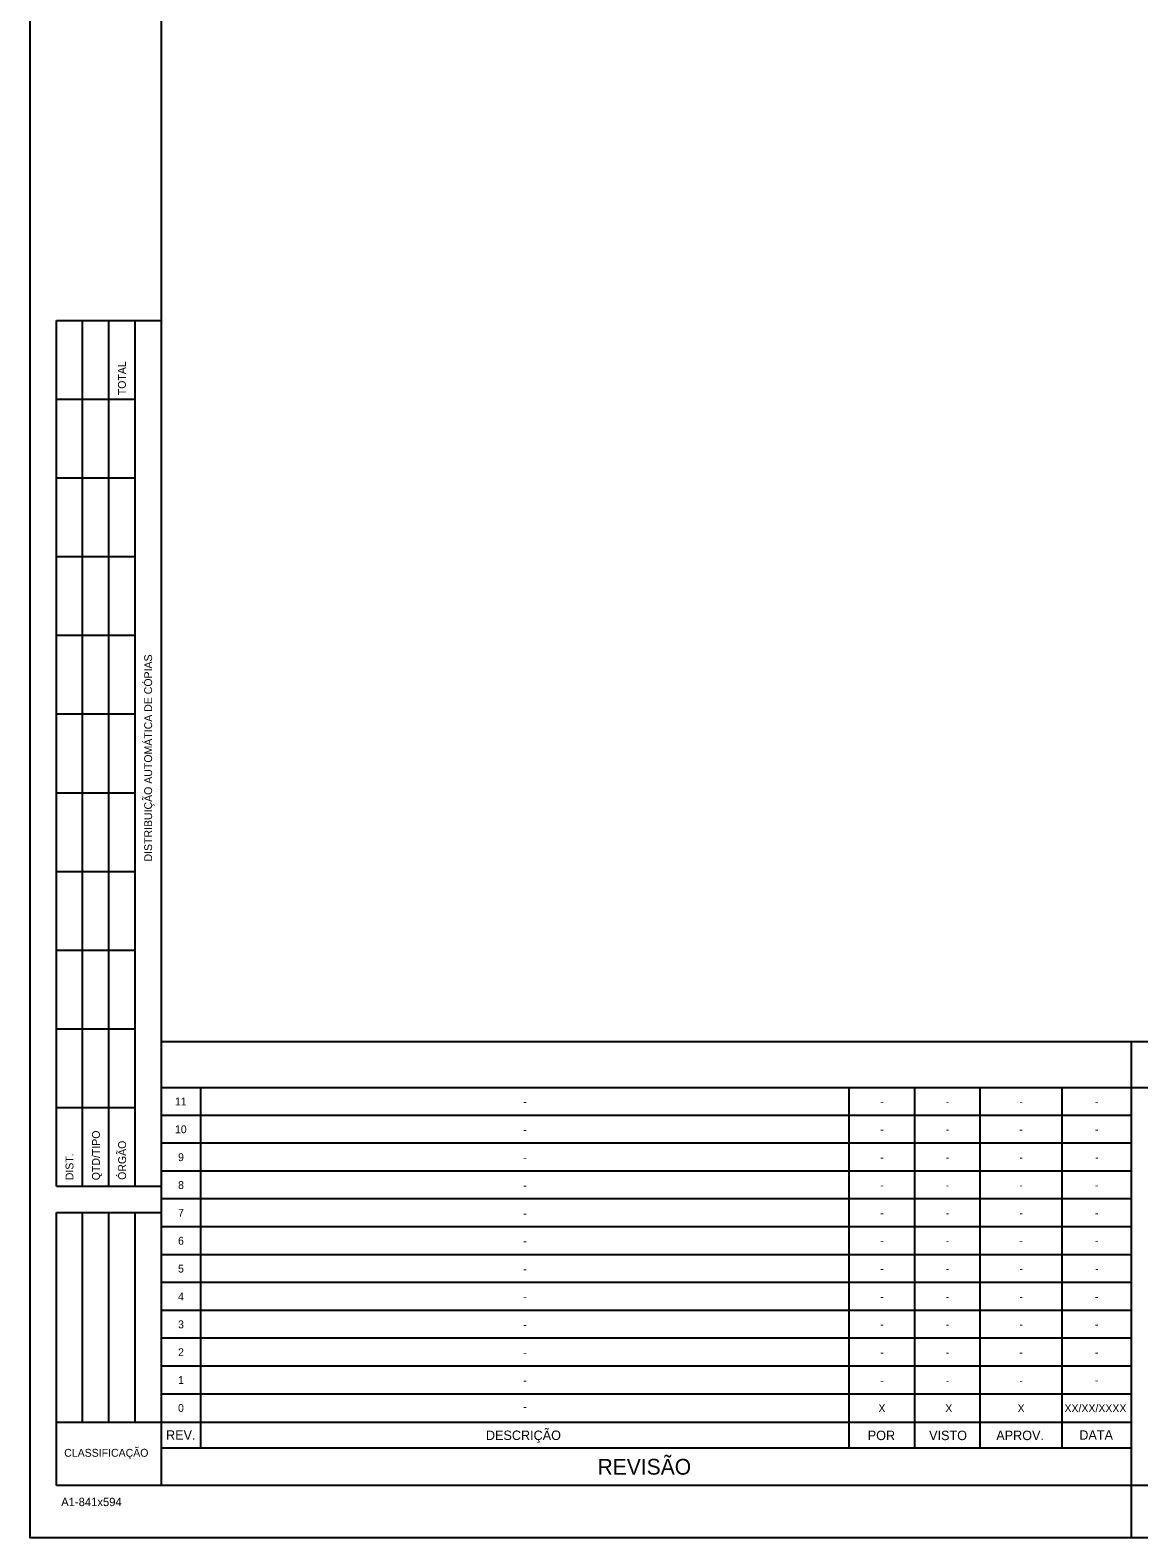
# Model space of a CAD drawing. Extents: x -1349 to -508, y 286 to 880.
# Drawn here: x -1349 to -1137.7, y 285.8 to 573.1 of the extents above; entities that cross this region are included whole.
import ezdxf

# ---------------------------------------------------------------- set-up
doc = ezdxf.new("R2010")
doc.units = 0
doc.layers.add('FORMATO', color=7, linetype='Continuous')
doc.layers.add('TEXTO', color=7, linetype='Continuous')

msp = doc.modelspace()

# ---------------------------------------------------------------- linework, layer by layer
at = {"layer": 'FORMATO'}
msp.add_line((-518.04, 295.82), (-1344.05, 295.82), dxfattribs=at)
msp.add_lwpolyline([(-1349.05, 879.82), (-508.05, 879.82), (-508.05, 285.82), (-1349.05, 285.82)], close=True, dxfattribs=at)
for points in [[(-518.04, 295.82), (-518.04, 869.82), (-1324.05, 869.82), (-1324.05, 295.82)], [(-1344.05, 352.82), (-1344.05, 517.82)], [(-1344.05, 517.82), (-1324.05, 517.82)], [(-1339.05, 352.82), (-1339.05, 517.82)], [(-1334.05, 352.82), (-1334.05, 517.82)], [(-1329.05, 352.82), (-1329.05, 517.82)], [(-1344.05, 502.82), (-1329.05, 502.82)], [(-1344.05, 487.82), (-1329.05, 487.82)], [(-1344.05, 472.82), (-1329.05, 472.82)], [(-1344.05, 457.82), (-1329.05, 457.82)], [(-1344.05, 442.82), (-1329.05, 442.82)], [(-1344.05, 427.82), (-1329.05, 427.82)], [(-1344.05, 412.82), (-1329.05, 412.82)], [(-1344.05, 397.82), (-1329.05, 397.82)], [(-1344.05, 382.82), (-1329.05, 382.82)], [(-518.04, 380.36), (-1324.05, 380.36)], [(-1139.05, 295.82), (-1139.05, 380.36)], [(-1324.05, 371.63), (-693.05, 371.63)], [(-1316.49, 302.91), (-1316.49, 371.63)], [(-1192.88, 302.91), (-1192.88, 371.63)], [(-1180.39, 302.91), (-1180.39, 371.63)], [(-1167.9, 302.91), (-1167.9, 371.63)], [(-1152.31, 302.91), (-1152.31, 371.63)], [(-1344.05, 367.82), (-1329.05, 367.82)], [(-1139.05, 366.32), (-1324.05, 366.32)], [(-1139.05, 361.01), (-1324.05, 361.01)], [(-1139.05, 355.7), (-1324.05, 355.7)], [(-1344.05, 352.82), (-1324.05, 352.82)], [(-1344.05, 295.82), (-1344.05, 347.82)], [(-1344.05, 347.82), (-1324.05, 347.82)], [(-1339.05, 307.82), (-1339.05, 347.82)], [(-1334.05, 307.82), (-1334.05, 347.82)], [(-1329.05, 307.82), (-1329.05, 347.82)], [(-1139.05, 350.39), (-1324.05, 350.39)], [(-1139.05, 345.08), (-1324.05, 345.08)], [(-1139.05, 339.77), (-1324.05, 339.77)], [(-1139.05, 334.46), (-1324.05, 334.46)], [(-1139.05, 329.15), (-1324.05, 329.15)], [(-1139.05, 323.84), (-1324.05, 323.84)], [(-1139.05, 318.53), (-1324.05, 318.53)], [(-1139.05, 313.22), (-1324.05, 313.22)], [(-1324.05, 307.82), (-1344.05, 307.82)], [(-1139.05, 307.82), (-1324.05, 307.82)], [(-1139.05, 302.91), (-1324.05, 302.91)], [(-1139.05, 285.82), (-1139.05, 295.82)]]:
    msp.add_lwpolyline(points, dxfattribs=at)

# ---------------------------------------------------------------- texts
for s, height, rotation, p in [('TOTAL', 1.5, 90, (-1330.8, 503.56)), ('DISTRIBUIÇÃO AUTOMÁTICA DE CÓPIAS', 1.5, 90, (-1325.8, 414.7)), ('QTD/TIPO', 1.5, 90, (-1335.75, 353.96)), ('ÓRGÃO', 1.5, 90, (-1330.76, 354.04)), ('DIST.', 1.5, 90, (-1340.8, 353.97)), ('REV.', 1.8, 360, (-1323.14, 304.51)), ('DESCRIÇÃO', 1.8, 360, (-1262.16, 304.46)), ('POR', 1.8, 360, (-1189.36, 304.44)), ('VISTO', 1.8, 360, (-1177.66, 304.44)), ('APROV.', 1.8, 360, (-1164.86, 304.44)), ('DATA', 1.8, 360, (-1149.03, 304.51)), ('CLASSIFICAÇÃO', 1.5, 360, (-1342.55, 301.27)), ('REVISÃO', 3, 360, (-1240.87, 297.86))]:
    msp.add_text(s, height=height, rotation=rotation, dxfattribs=at).set_placement(p)
msp.add_text('A1-841x594', height=1.6, dxfattribs=at).set_placement((-1343.13, 291.86))
at = {"layer": 'TEXTO'}
for s, p in [('11', (-1321.44, 368.23)), ('-', (-1255.04, 368.18)), ('-', (-1186.98, 368.22)), ('-', (-1174.49, 368.22)), ('-', (-1160.45, 368.22)), ('-', (-1146.03, 368.22)), ('10', (-1321.44, 362.92)), ('-', (-1255.04, 362.87)), ('-', (-1186.98, 362.91)), ('-', (-1174.49, 362.91)), ('-', (-1160.46, 362.91)), ('-', (-1146.03, 362.91)), ('9', (-1320.85, 357.61)), ('-', (-1255.04, 357.56)), ('-', (-1186.98, 357.6)), ('-', (-1174.49, 357.6)), ('-', (-1160.45, 357.6)), ('-', (-1146.02, 357.6)), ('8', (-1320.85, 352.3)), ('-', (-1255.04, 352.25)), ('-', (-1186.98, 352.29)), ('-', (-1174.49, 352.29)), ('-', (-1160.45, 352.29)), ('-', (-1146.03, 352.29)), ('7', (-1320.85, 346.99)), ('-', (-1186.98, 346.98)), ('-', (-1174.49, 346.98)), ('-', (-1160.45, 346.98)), ('-', (-1146.03, 346.98)), ('-', (-1255.04, 346.94)), ('6', (-1320.85, 341.68)), ('-', (-1255.04, 341.63)), ('-', (-1186.99, 341.67)), ('-', (-1174.49, 341.67)), ('-', (-1160.46, 341.67)), ('-', (-1146.03, 341.67)), ('5', (-1320.85, 336.37)), ('-', (-1255.04, 336.32)), ('-', (-1186.98, 336.37)), ('-', (-1174.49, 336.36)), ('-', (-1160.45, 336.36)), ('-', (-1146.02, 336.36)), ('4', (-1320.85, 331.06)), ('-', (-1255.04, 331.01)), ('-', (-1186.98, 331.06)), ('-', (-1174.49, 331.06)), ('-', (-1160.45, 331.05)), ('-', (-1146.03, 331.05)), ('3', (-1320.85, 325.75)), ('-', (-1255.04, 325.7)), ('-', (-1186.98, 325.75)), ('-', (-1174.49, 325.75)), ('-', (-1160.45, 325.75)), ('-', (-1146.03, 325.75)), ('2', (-1320.85, 320.44)), ('-', (-1255.04, 320.39)), ('-', (-1186.99, 320.44)), ('-', (-1174.49, 320.44)), ('-', (-1160.46, 320.44)), ('-', (-1146.03, 320.44)), ('1', (-1320.85, 315.13)), ('-', (-1255.04, 315.08)), ('-', (-1186.98, 315.06)), ('-', (-1174.49, 315.06)), ('-', (-1160.45, 315.06)), ('-', (-1146.03, 315.13)), ('0', (-1320.85, 309.82)), ('-', (-1255.04, 310.09)), ('X', (-1187.33, 309.77)), ('X', (-1174.57, 309.77)), ('X', (-1160.8, 309.77)), ('XX/XX/XXXX', (-1151.86, 309.77))]:
    msp.add_text(s, height=1.5, rotation=359.9989, dxfattribs=at).set_placement(p)

doc.saveas('drawing.dxf')
